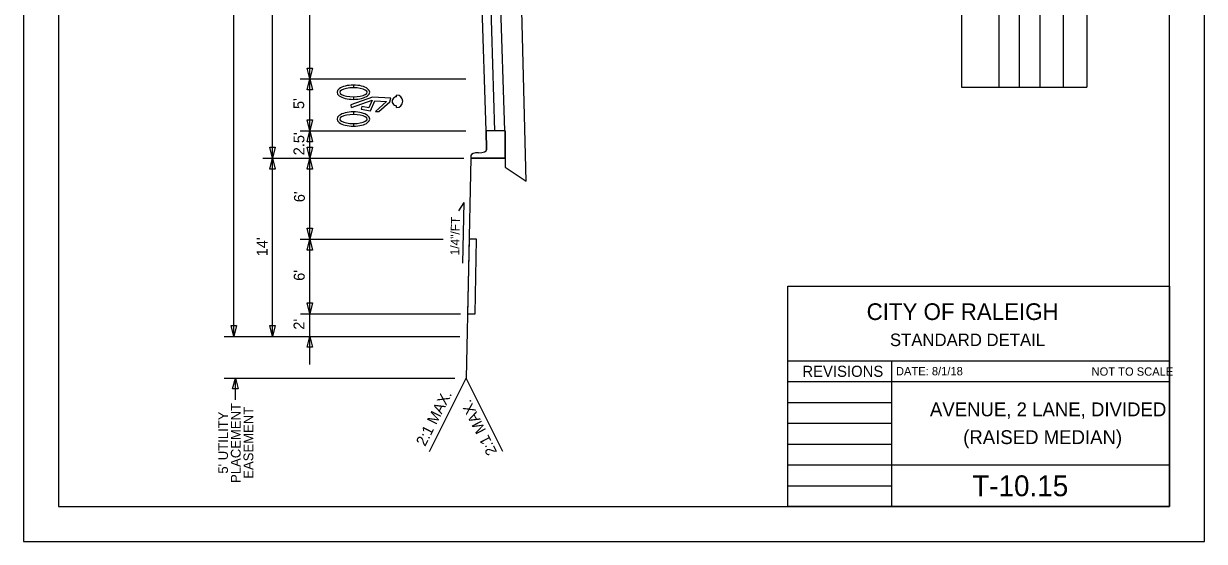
# Model space of a CAD drawing. Extents: x 0 to 8.5, y 0 to 11.
# Drawn here: x 0 to 8.5, y 0 to 3.73 of the extents above; entities that cross this region are included whole.
import ezdxf

# ---------------------------------------------------------------- set-up
doc = ezdxf.new("R2010")
doc.units = 0
for name, color, linetype in [('MARK BICYCLE SYMBOL CELL', 7, 'Continuous'), ('Old_Level_1', 7, 'Continuous'), ('Old_Level_11', 7, 'Continuous'), ('Old_Level_5', 7, 'Continuous'), ('Prop Shade Light', 7, 'Continuous'), ('SHEET BORDER', 7, 'Continuous'), ('SHEET NOTES', 7, 'Continuous'), ('SHEET TITLE BLOCK LINE', 7, 'Continuous'), ('SHEET TITLE BLOCK TEXT', 7, 'Continuous'), ('SHEET TRIM BORDER', 7, 'Continuous'), ('Typical Pavement Slope Information CELL', 7, 'Continuous')]:
    doc.layers.add(name, color=color, linetype=linetype)

msp = doc.modelspace()

# ---------------------------------------------------------------- linework, layer by layer
at = {"layer": 'MARK BICYCLE SYMBOL CELL'}
for p, q in [((2.3742, 3.2836), (2.3742, 3.2644)), ((2.3742, 3.2836), (2.3742, 3.2644)), ((2.5117, 3.1964), (2.3544, 3.141)), ((2.3606, 3.1233), (2.5089, 3.1755)), ((2.3742, 3.2), (2.3742, 3.1808)), ((2.3742, 3.2), (2.3742, 3.1808)), ((2.5089, 3.1755), (2.485, 3.1189)), ((2.4961, 3.0974), (2.5272, 3.1711)), ((2.6432, 3.1886), (2.5117, 3.1964)), ((2.5272, 3.1711), (2.613, 3.166)), ((2.613, 3.166), (2.5321, 3.0934)), ((2.5565, 3.0934), (2.6357, 3.1639)), ((2.6357, 3.1639), (2.6432, 3.1886)), ((2.685, 3.1992), (2.685, 3.2113)), ((2.685, 3.1992), (2.685, 3.2113)), ((2.3544, 3.141), (2.3586, 3.1227)), ((2.3742, 3.0907), (2.3742, 3.0715)), ((2.3742, 3.0907), (2.3742, 3.0715)), ((2.435, 3.1296), (2.4311, 3.1113)), ((2.4311, 3.1113), (2.4961, 3.0974)), ((2.485, 3.1189), (2.435, 3.1296)), ((2.5321, 3.0934), (2.5565, 3.0934)), ((2.685, 3.1224), (2.685, 3.1345)), ((2.685, 3.1224), (2.685, 3.1345)), ((2.3742, 3.0072), (2.3742, 2.988)), ((2.3742, 3.0072), (2.3742, 2.988))]:
    msp.add_line(p, q, dxfattribs=at)
for radius, start, end in [(0.0324, 90.00002, 270.00002), (0.0444, 270.00002, 90.00002), (0.0444, 270.00002, 90.00002)]:
    msp.add_arc((2.685, 3.1669), radius, start, end, dxfattribs=at)
for centre, major_axis, ratio, start_param, end_param in [((2.3742, 3.2322), (-0.1179, 0), 0.435841, 4.712389, 7.853982), ((2.3742, 3.2322), (-0.0987, 0), 0.325967, 4.712389, 7.853982), ((2.3742, 3.2322), (-0.1179, 0), 0.435841, 1.570796, 4.712389), ((2.3742, 3.2322), (-0.0987, 0), 0.325967, 1.570796, 4.712389), ((2.3742, 3.0393), (-0.1179, 0), 0.435841, 4.712389, 7.853982), ((2.3742, 3.0393), (-0.0987, 0), 0.325967, 4.712389, 7.853982), ((2.3742, 3.0393), (-0.1179, 0), 0.435841, 1.570796, 4.712389), ((2.3742, 3.0393), (-0.0987, 0), 0.325967, 1.570796, 4.712389)]:
    msp.add_ellipse(centre, major_axis=major_axis, ratio=ratio, start_param=start_param, end_param=end_param, dxfattribs=at)
at = {"layer": 'Old_Level_1'}
for p, q in [((3.6172, 2.5926), (3.559, 4.9711)), ((3.3287, 2.9545), (3.2727, 4.6877)), ((3.393, 2.9545), (3.338, 4.6877)), ((3.4646, 2.9545), (3.4096, 4.6877)), ((3.4665, 2.9545), (3.3287, 2.9545)), ((3.3331, 2.817), (3.3287, 2.9545)), ((3.4665, 2.9545), (3.4666, 2.7579)), ((3.4665, 2.9545), (3.4666, 2.7579)), ((3.2196, 2.7579), (3.1867, 1.1755)), ((3.2196, 2.7775), (3.2196, 2.7579)), ((3.4666, 2.7579), (3.2196, 2.7579)), ((3.4666, 2.7579), (3.4666, 2.6931)), ((3.4666, 2.6931), (3.6166, 2.593)), ((2.9224, 0.6469), (3.1867, 1.1755)), ((3.4509, 0.6469), (3.1867, 1.1755))]:
    msp.add_line(p, q, dxfattribs=at)
for centre, major_axis, ratio, start_param, end_param in [((3.2728, 2.8168), (-0.0603, 0), 0.32599, 1.618928, 3.151961), ((3.2784, 2.7775), (-0.059, 0), 0.333333, 4.760521, 6.283197)]:
    msp.add_ellipse(centre, major_axis=major_axis, ratio=ratio, start_param=start_param, end_param=end_param, dxfattribs=at)
at = {"layer": 'Old_Level_11'}
for p, q in [((1.7921, 1.4756), (1.7921, 9.5209)), ((1.5138, 1.4756), (1.5135, 9.4997)), ((2.0606, 3.3276), (2.0606, 4.6883)), ((1.9906, 3.3276), (3.1837, 3.3276)), ((2.0606, 2.9546), (2.0606, 3.3276)), ((1.9906, 2.9546), (3.1837, 2.9545)), ((2.0607, 2.7579), (2.0606, 2.9546)), ((1.7225, 2.7579), (3.1697, 2.7579)), ((2.0607, 2.1749), (2.0607, 2.7972)), ((1.9907, 2.1749), (3.0194, 2.1748)), ((2.0607, 1.7837), (2.0607, 2.1748)), ((2.0607, 1.2734), (2.0607, 1.7837)), ((1.9936, 1.6383), (3.144, 1.6382)), ((1.4438, 1.4756), (3.14, 1.4756)), ((1.4438, 1.1755), (3.104, 1.1755)), ((1.5241, 1.0178), (1.5241, 1.1755))]:
    msp.add_line(p, q, dxfattribs=at)
for points in [[(2.0803, 3.4063), (2.0606, 3.3276), (2.0409, 3.4063)], [(2.041, 3.2489), (2.0606, 3.3276), (2.0803, 3.2489)], [(2.0803, 3.0333), (2.0606, 2.9546), (2.0409, 3.0333)], [(2.041, 2.8759), (2.0606, 2.9546), (2.0803, 2.8759)], [(1.8118, 2.8366), (1.7921, 2.7579), (1.7724, 2.8366)], [(2.0803, 2.8366), (2.0607, 2.7579), (2.041, 2.8366)], [(1.7724, 2.6793), (1.7921, 2.7579), (1.8118, 2.6793)], [(2.041, 2.6792), (2.0607, 2.7579), (2.0803, 2.6792)], [(2.0803, 2.2535), (2.0607, 2.1748), (2.041, 2.2535)], [(2.041, 2.0962), (2.0607, 2.1748), (2.0803, 2.0962)], [(2.0804, 1.7169), (2.0607, 1.6383), (2.041, 1.7169)], [(1.5335, 1.5543), (1.5138, 1.4756), (1.4941, 1.5543)], [(1.8117, 1.5543), (1.7921, 1.4756), (1.7724, 1.5543)], [(2.041, 1.3969), (2.0607, 1.4756), (2.0804, 1.3969)], [(1.5044, 1.0969), (1.5241, 1.1755), (1.5437, 1.0969)]]:
    msp.add_lwpolyline(points, close=True, dxfattribs=at)
at = {"layer": 'Old_Level_5'}
for points in [[(3.2194, 2.7775), (3.2196, 2.7579), (3.4666, 2.7579), (3.4665, 2.9545), (3.3292, 2.9545)], [(3.3292, 2.9545), (3.3287, 2.9545), (3.3331, 2.817)], [(3.2757, 2.7972), (3.2756, 2.7972)]]:
    msp.add_lwpolyline(points, dxfattribs=at)
for centre, major_axis, ratio, start_param, end_param in [((3.2728, 2.8168), (-0.0603, 0), 0.32599, 1.618928, 3.151961), ((3.2784, 2.7775), (-0.059, 0), 0.333333, 4.760521, 6.283197)]:
    msp.add_ellipse(centre, major_axis=major_axis, ratio=ratio, start_param=start_param, end_param=end_param, dxfattribs=at)
at = {"layer": 'Prop Shade Light'}
msp.add_lwpolyline([(3.2074, 2.1748), (3.1963, 1.6375), (3.2496, 1.6374), (3.2601, 2.1748)], close=True, dxfattribs=at)
at = {"layer": 'SHEET BORDER'}
msp.add_lwpolyline([(8.25, 10.75), (0.25, 10.75), (0.25, 0.25), (8.25, 0.25)], close=True, dxfattribs=at)
at = {"layer": 'SHEET NOTES'}
for p, q in [((6.7507, 7.8993), (6.7507, 3.2689)), ((7.0191, 7.8993), (7.0191, 3.2689)), ((7.1659, 7.8993), (7.1659, 3.2689)), ((7.3146, 7.8993), (7.3146, 3.2689)), ((7.484, 7.8993), (7.484, 3.2689)), ((7.6534, 7.8993), (7.6534, 3.2689)), ((6.7507, 3.2689), (7.6534, 3.2689))]:
    msp.add_line(p, q, dxfattribs=at)
at = {"layer": 'SHEET TITLE BLOCK LINE'}
for p, q in [((5.5002, 1.2999), (8.25, 1.2999)), ((6.2501, 0.25), (6.2501, 1.2999)), ((5.5002, 1.1499), (8.25, 1.1499)), ((5.5002, 0.9999), (6.2501, 0.9999)), ((5.5002, 0.85), (6.2501, 0.85)), ((5.5002, 0.7), (6.2501, 0.7)), ((5.5002, 0.55), (6.2501, 0.55)), ((6.2501, 0.55), (8.25, 0.55)), ((5.5002, 0.4), (6.2501, 0.4))]:
    msp.add_line(p, q, dxfattribs=at)
msp.add_lwpolyline([(8.25, 0.25), (5.5002, 0.25), (5.5002, 1.8359), (8.25, 1.8359)], close=True, dxfattribs=at)
at = {"layer": 'SHEET TRIM BORDER'}
msp.add_lwpolyline([(8.5, 11), (0, 11), (0, 0), (8.5, 0)], close=True, dxfattribs=at)
at = {"layer": 'Typical Pavement Slope Information CELL'}
for q in [(3.1311, 2.3781), (3.1593, 2.0022)]:
    msp.add_line((3.1681, 2.4393), q, dxfattribs=at)

# ---------------------------------------------------------------- texts
at = {"layer": 'Old_Level_11'}
for s, height, rotation, p in [("5'", 0.07823, 90.00211, (2.0198, 3.1112)), ("2.5'", 0.07823, 90.00211, (2.0211, 2.7786)), ("6'", 0.07823, 90.00211, (2.0245, 2.4409)), ('1/4"/FT', 0.06402, 88.85203, (3.1353, 2.0579)), ("14'", 0.07823, 90, (1.7561, 2.0519)), ("6'", 0.07823, 90.00211, (2.0232, 1.8751)), ("2'", 0.07823, 90.00211, (2.0213, 1.5235)), ('2:1 MAX.', 0.07823, 62.953, (2.8903, 0.6786)), ('PLACEMENT', 0.07041, 90, (1.5623, 0.4206)), ('EASEMENT', 0.07041, 90, (1.6534, 0.4507)), ('2:1 MAX.', 0.07823, 117.047, (3.4102, 0.6433)), ("5' UTILITY", 0.07041, 90, (1.4712, 0.4872))]:
    msp.add_text(s, height=height, rotation=rotation, dxfattribs=at).set_placement(p)
at = {"layer": 'SHEET TITLE BLOCK TEXT'}
for s, height, p in [('CITY OF RALEIGH', 0.12, (6.0686, 1.5932)), ('STANDARD DETAIL', 0.09, (6.2364, 1.4053)), ('REVISIONS', 0.08, (5.6059, 1.184)), ('DATE: 8/1/18', 0.06, (6.2796, 1.195)), ('NOT TO SCALE', 0.06, (7.6877, 1.1922)), ('AVENUE, 2 LANE, DIVIDED', 0.100002, (6.5242, 0.9)), ('(RAISED MEDIAN)', 0.100002, (6.7635, 0.7)), ('T-10.15', 0.15, (6.8288, 0.325))]:
    msp.add_text(s, height=height, dxfattribs=at).set_placement(p)

doc.saveas('drawing.dxf')
